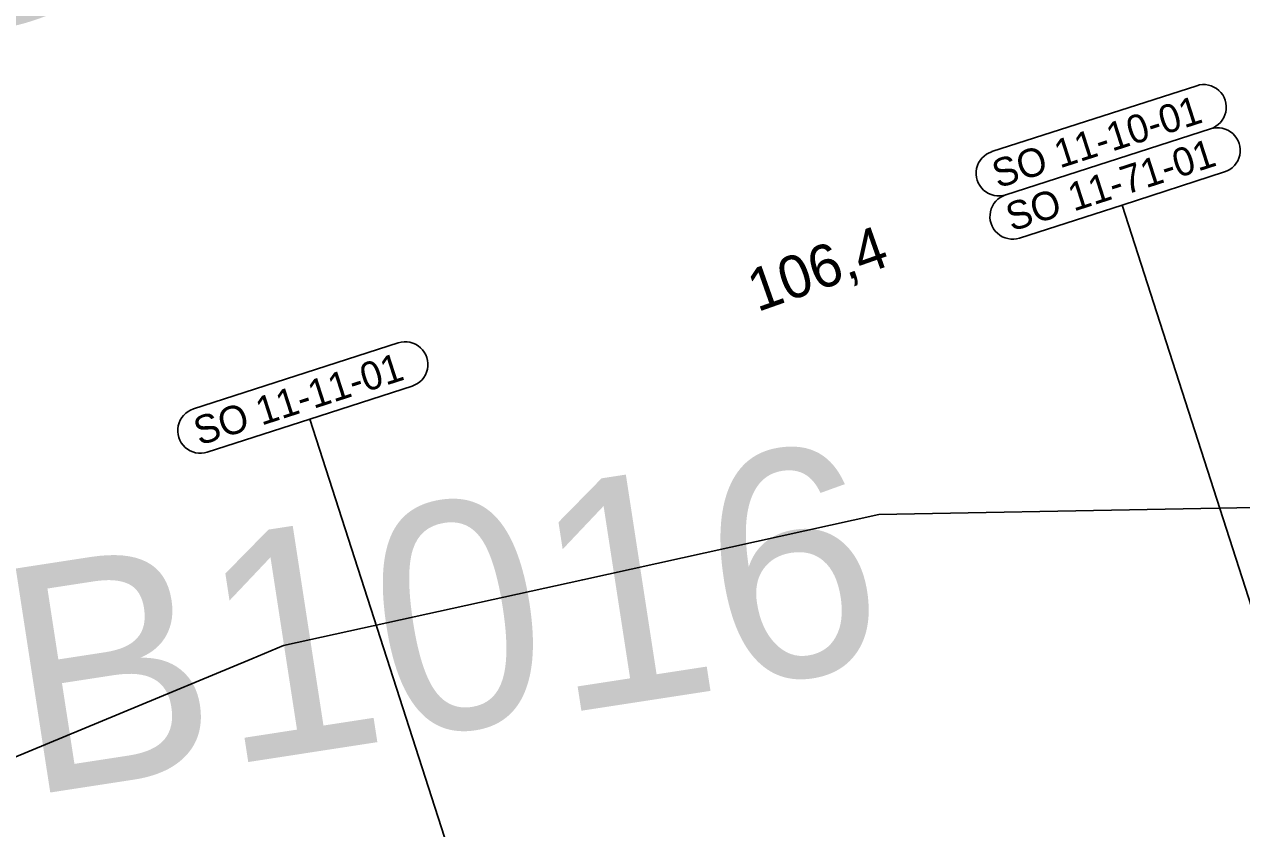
# Model space of a CAD drawing. Extents: x -759005 to -757278, y -1175311 to -1173953.
# Drawn here: x -758275 to -758167.6, y -1174754.3 to -1174683.4 of the extents above; entities that cross this region are included whole.
import ezdxf

# ---------------------------------------------------------------- set-up
doc = ezdxf.new("R2010")
doc.units = 0
for name, color, linetype in [('_NOR-popis', 7, 'Continuous'), ('G_Obvod stavby', 7, 'Continuous'), ('Vrstva 53', 7, 'Continuous'), ('Vrstva 62', 7, 'Continuous'), ('Vrstva 7', 7, 'Continuous')]:
    doc.layers.add(name, color=color, linetype=linetype)

msp = doc.modelspace()

# ---------------------------------------------------------------- linework, layer by layer
at = {"layer": '_NOR-popis'}
for points in [[(-758189.66, -1174694.59), (-758171.57, -1174688.77)], [(-758188.43, -1174698.4), (-758170.35, -1174692.58)], [(-758170.35, -1174692.58), (-758179.39, -1174695.49)], [(-758179.39, -1174695.49), (-758188.43, -1174698.4)], [(-758169.12, -1174696.38), (-758178.16, -1174699.3), (-758157.53, -1174763.36)], [(-758178.16, -1174699.3), (-758187.21, -1174702.21)], [(-758260.13, -1174717.29), (-758242.04, -1174711.47)], [(-758240.81, -1174715.27), (-758249.86, -1174718.19), (-758235.71, -1174762.12)], [(-758249.86, -1174718.19), (-758258.9, -1174721.1)]]:
    msp.add_lwpolyline(points, dxfattribs=at)
for centre, start, end in [((-758170.96, -1174690.67), 287.8533, 107.854), ((-758169.73, -1174694.48), 287.8533, 107.854), ((-758189.04, -1174696.5), 107.854, 287.8547), ((-758187.82, -1174700.31), 107.854, 287.8547), ((-758241.43, -1174713.37), 287.8533, 107.854), ((-758259.51, -1174719.2), 107.854, 287.8547)]:
    msp.add_arc(centre, 2, start, end, dxfattribs=at)
at = {"layer": 'G_Obvod stavby'}
msp.add_lwpolyline([(-758392.72, -1174840.76), (-758391.23, -1174838.56), (-758368.37, -1174821.64), (-758340.31, -1174807.33), (-758320.27, -1174796.89), (-758301, -1174790.21), (-758267.96, -1174782.93), (-758224.96, -1174775.27), (-758184.87, -1174772.83), (-758142.71, -1174770.26), (-758089.84, -1174768.68), (-758106.02, -1174731.44), (-758149.09, -1174725.67), (-758199.62, -1174726.6), (-758225.76, -1174732.36), (-758252.17, -1174738.18), (-758254.97, -1174739.34), (-758266.58, -1174744.16), (-758279.45, -1174749.49), (-758302.42, -1174759.02), (-758331.68, -1174770.24), (-758367.17, -1174799.81), (-758405.64, -1174832.2)], dxfattribs=at)

# ---------------------------------------------------------------- texts
at = {"layer": '_NOR-popis'}
for s, p in [('SO 11-10-01', (-758189.13, -1174697.84)), ('SO 11-71-01', (-758187.91, -1174701.65)), ('SO 11-11-01', (-758259.6, -1174720.54))]:
    msp.add_text(s, height=2.5, rotation=17.854, dxfattribs=at).set_placement(p)
at = {"layer": 'Vrstva 53'}
msp.add_text('GB1016', height=20, rotation=8.7502, dxfattribs=at).set_placement((-758295.49, -1174754.64))
at = {"layer": 'Vrstva 62'}
msp.add_text('106,3', height=36, rotation=17.7485, dxfattribs=at).set_placement((-758376.56, -1174715.23))
at = {"layer": 'Vrstva 7'}
msp.add_text('106,4', height=3.75, rotation=19.4575, dxfattribs=at).set_placement((-758210.35, -1174708.76))

doc.saveas('drawing.dxf')
